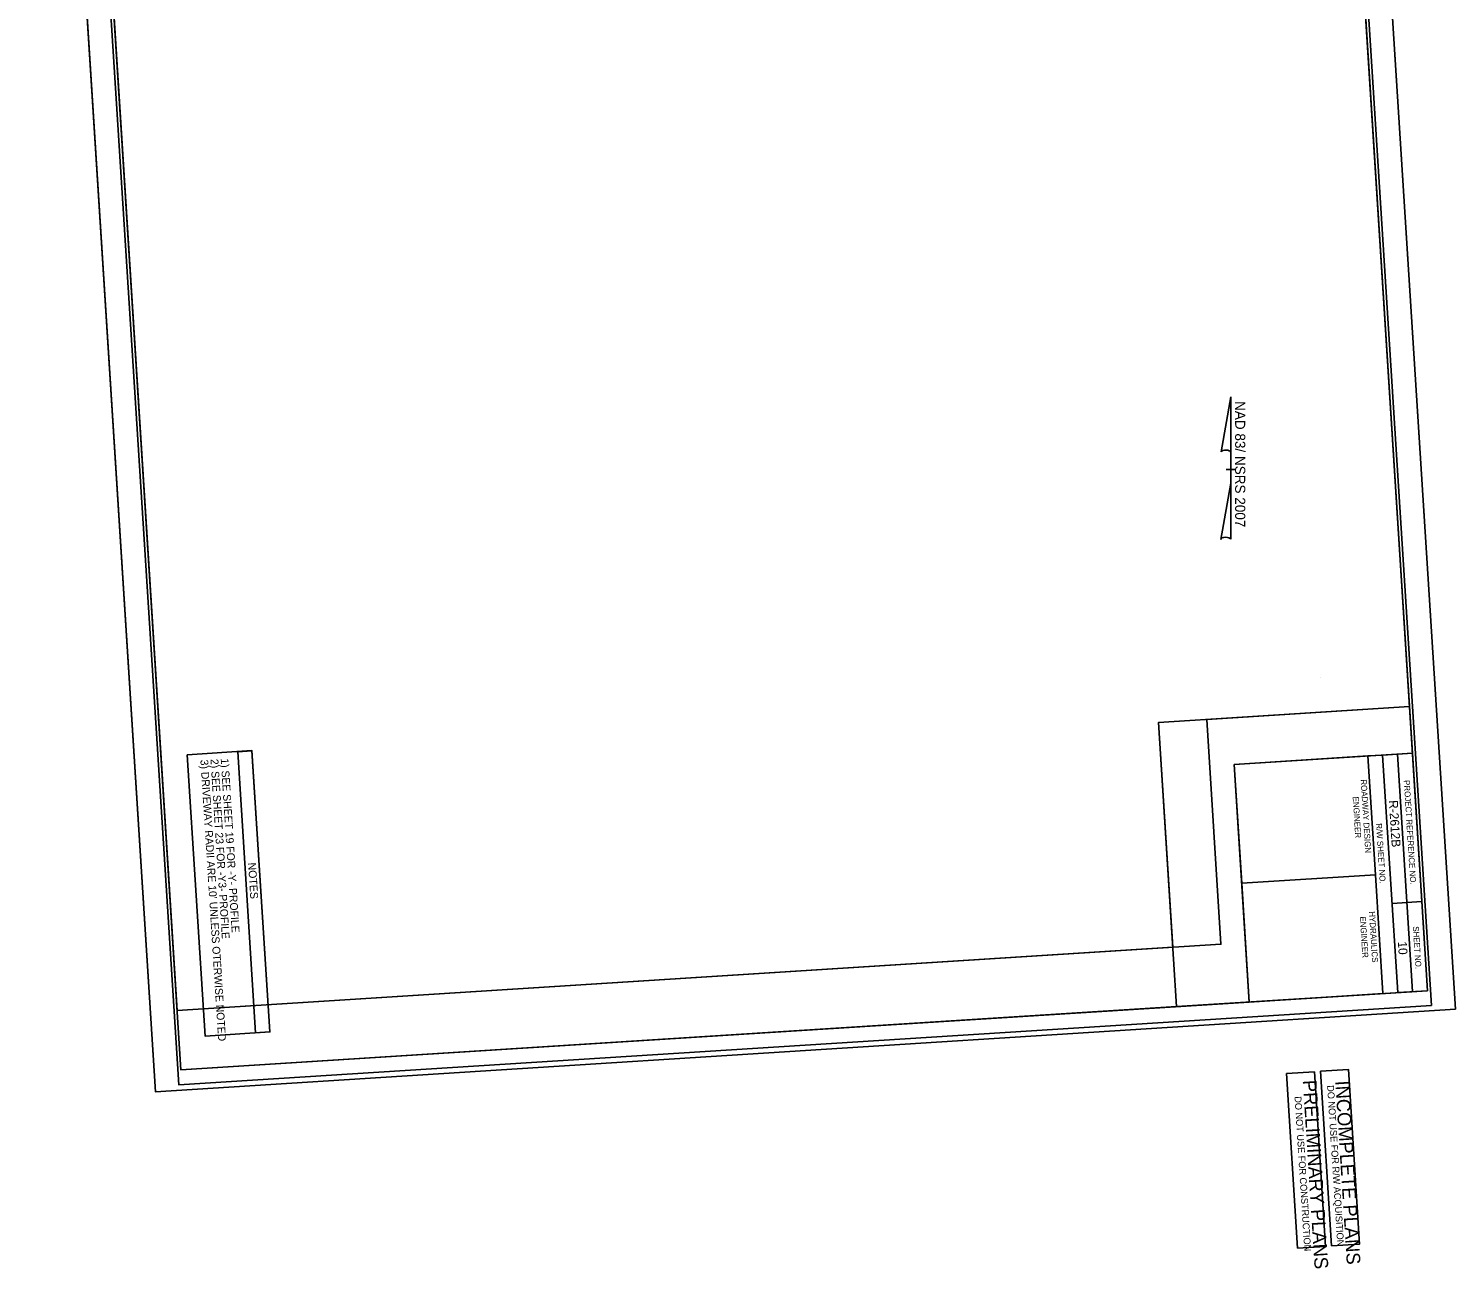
# Model space of a CAD drawing. Extents: x 1780418 to 1781618, y 810313 to 812397.
# Drawn here: x 1780418 to 1781618, y 810313 to 811355 of the extents above; entities that cross this region are included whole.
import ezdxf

# ---------------------------------------------------------------- set-up
doc = ezdxf.new("R2010")
doc.units = 0
for name, color, linetype in [('Prop Easement Aerial Utility', 7, 'Continuous'), ('Prop Easement Danger Tree Area', 7, 'Continuous'), ('Prop Easement Permanent Drainage', 7, 'Continuous'), ('Prop Easement Permanent Drainage Station Offsets', 7, 'Continuous'), ('Prop Easement Permanent Drainage Utility', 7, 'Continuous'), ('Prop Easement Permanent Drainage Utility Station Offsets', 7, 'Continuous'), ('Prop Easement Permanent Utility', 7, 'Continuous'), ('Prop Easement Temporary Drainage', 7, 'Continuous'), ('Prop Easement Temporary Drainage Station Offsets', 7, 'Continuous'), ('Prop Easement Temporary Utility', 7, 'Continuous'), ('Prop Parcel Number CELL', 7, 'Continuous'), ('Prop ROW CA Lines', 7, 'Continuous'), ('Prop ROW Marker CELL', 7, 'Continuous'), ('Prop ROW Station Offsets', 7, 'Continuous')]:
    doc.layers.add(name, color=color, linetype=linetype)

msp = doc.modelspace()

# ---------------------------------------------------------------- linework, layer by layer
at = {"layer": 'Prop Easement Aerial Utility'}
for p, q in [((1781617.8, 810530.9), (1781511, 812211)), ((1780418.2, 812141.5), (1780525, 810461.4))]:
    msp.add_line(p, q, dxfattribs=at)
at = {"layer": 'Prop Easement Danger Tree Area'}
msp.add_lwpolyline([(1781504.4, 810478.7), (1781527.9, 810480.1), (1781537.2, 810333.4), (1781513.7, 810332)], close=True, dxfattribs=at)
at = {"layer": 'Prop Easement Permanent Drainage'}
msp.add_lwpolyline([(1781475.8, 810476.7), (1781499.3, 810478.2), (1781508.6, 810331.5), (1781485.1, 810330)], close=True, dxfattribs=at)
at = {"layer": 'Prop Easement Permanent Drainage Utility'}
msp.add_line((1781504.5, 810809.4), (1781504.5, 810809.4), dxfattribs=at)
at = {"layer": 'Prop Easement Permanent Drainage Utility Station Offsets'}
for points in [[(1780551.7, 810744.8), (1780566.7, 810508.3), (1780621.1, 810511.7), (1780606, 810748.3)], [(1780594.1, 810747.2), (1780609.1, 810510.9), (1780621.1, 810511.7), (1780606, 810748)]]:
    msp.add_lwpolyline(points, close=True, dxfattribs=at)
at = {"layer": 'Prop Easement Permanent Utility'}
msp.add_lwpolyline([(1780454.4, 811926.9), (1780543.2, 810529.7), (1781380.1, 810582.9), (1781368.1, 810771.8), (1781579.1, 810785.2), (1781502.3, 811993.5)], close=True, dxfattribs=at)
at = {"layer": 'Prop Easement Temporary Drainage'}
for p, q in [((1781556.6, 810744.5), (1781544.1, 810743.7)), ((1781556.6, 810744.5), (1781569.3, 810544.8)), ((1781556.6, 810744.5), (1781569.3, 810544.8)), ((1781569.1, 810745.3), (1781581.8, 810545.6)), ((1781550.5, 810643.8), (1781438.2, 810636.7)), ((1781589.5, 810621.3), (1781564.5, 810619.7))]:
    msp.add_line(p, q, dxfattribs=at)
for points in [[(1781594.3, 810546.4), (1781499.2, 812043.4), (1780451.3, 811976.8), (1780546.4, 810479.8)], [(1780451.3, 811976.8), (1781499.1, 812043.4), (1781581.6, 810746.1), (1781431.9, 810736.5), (1781444.5, 810536.9), (1780546.4, 810479.8)], [(1781544.1, 810743.7), (1781550.5, 810643.8), (1781438.2, 810636.7), (1781431.9, 810736.5)], [(1781581.6, 810746.1), (1781594.3, 810546.4), (1781569.3, 810544.8), (1781556.6, 810744.5)], [(1781550.5, 810643.8), (1781556.8, 810544), (1781444.5, 810536.9), (1781438.2, 810636.7)]]:
    msp.add_lwpolyline(points, close=True, dxfattribs=at)
at = {"layer": 'Prop Easement Temporary Drainage Station Offsets'}
for p, q in [((1781420.8, 810999.3), (1781429, 811045.6)), ((1781429.1, 811045.6), (1781429, 811045.6)), ((1781429.1, 811045.6), (1781429, 811045.6)), ((1781429.1, 811045.6), (1781429.1, 810997.8)), ((1781429.1, 810973), (1781429.1, 810999.2)), ((1781429.1, 810997.8), (1781429.1, 810999.2)), ((1781425.1, 810984.6), (1781425, 810984.6)), ((1781425.1, 810984.6), (1781433.1, 810984.6)), ((1781428.6, 810984.6), (1781425.1, 810984.6)), ((1781429.1, 810973), (1781420.7, 810925.8)), ((1781429.1, 810926), (1781429.1, 810973))]:
    msp.add_line(p, q, dxfattribs=at)
for centre, start_param, end_param in [((1781424.9, 810998.8), 0.216388, 2.908219), ((1781424.9, 810925.6), 0.201328, 3.141593)]:
    msp.add_ellipse(centre, major_axis=(4.23, -0.03), ratio=0.461098, start_param=start_param, end_param=end_param, dxfattribs=at)
at = {"layer": 'Prop Easement Temporary Utility'}
for points in [[(1781499.1, 812043.4), (1780451.3, 811976.8), (1780546.4, 810479.8), (1781383.2, 810533), (1781368.1, 810771.8), (1781579.1, 810785.2)], [(1781368.1, 810771.8), (1781383.2, 810533), (1781594.3, 810546.4), (1781579.1, 810785.2)]]:
    msp.add_lwpolyline(points, close=True, dxfattribs=at)
at = {"layer": 'Prop ROW CA Lines'}
msp.add_lwpolyline([(1780418.2, 812141.5), (1780525, 810461.4), (1781617.8, 810530.9), (1781511, 812211)], close=True, dxfattribs=at)
at = {"layer": 'Prop ROW Marker CELL'}
msp.add_lwpolyline([(1781518.9, 811732.4), (1780459, 811854.7), (1780543.2, 810529.7), (1781420.7, 810585.5), (1781408.7, 810774.4), (1781579.1, 810785.2)], close=True, dxfattribs=at)
at = {"layer": 'Prop ROW Station Offsets'}
msp.add_lwpolyline([(1780439, 812129.8), (1780544.7, 810467.2), (1781597.6, 810534.1), (1781491.9, 812196.7)], close=True, dxfattribs=at)

# ---------------------------------------------------------------- texts
at = {"layer": 'Prop Easement Danger Tree Area'}
for s, height, p in [('DO NOT USE FOR R/W ACQUISITION', 5.76, (1781509.9, 810466.8)), ('INCOMPLETE PLANS', 11.52, (1781516.7, 810470.5))]:
    msp.add_text(s, height=height, rotation=273.6363, dxfattribs=at).set_placement(p)
at = {"layer": 'Prop Easement Permanent Drainage'}
for s, height, p in [('PRELIMINARY PLANS', 11.52, (1781489.4, 810471)), ('DO NOT USE FOR CONSTRUCTION', 5.76, (1781482.5, 810457.5))]:
    msp.add_text(s, height=height, rotation=273.6363, dxfattribs=at).set_placement(p)
at = {"layer": 'Prop Easement Permanent Drainage Station Offsets'}
for s, height, p in [("3) DRIVEWAY RADII ARE 10' UNLESS OTERWISE NOTED", 6.56, (1780562.7, 810740.4)), ('2) SEE SHEET 23 FOR -Y3- PROFILE', 6.56, (1780571.2, 810741)), ('1) SEE SHEET 19 FOR -Y- PROFILE ', 6.56, (1780579.8, 810741.5)), ('NOTES', 6.64, (1780602.8, 810653.9))]:
    msp.add_text(s, height=height, rotation=273.6363, dxfattribs=at).set_placement(p)
at = {"layer": 'Prop Easement Temporary Drainage'}
for s, p in [('ROADWAY DESIGN', (1781538.1, 810723.9)), ('PROJECT REFERENCE NO.', (1781574.3, 810723.3)), ('ENGINEER', (1781531.4, 810709.4)), ('R/W SHEET NO.', (1781551, 810687)), ('ENGINEER', (1781537.4, 810608.7)), ('HYDRAULICS', (1781545.1, 810613)), ('SHEET NO.', (1781582, 810600.4))]:
    msp.add_text(s, height=5, rotation=273.6363, dxfattribs=at).set_placement(p)
at = {"layer": 'Prop Easement Temporary Drainage Station Offsets'}
msp.add_text('NAD 83/ NSRS 2007', height=8.5, rotation=270, dxfattribs=at).set_placement((1781432.6, 811042))
at = {"layer": 'Prop Parcel Number CELL'}
for s, p in [('R-2612B  ', (1781561.8, 810706.3)), ('10', (1781569.4, 810587.6))]:
    msp.add_text(s, height=7.5, rotation=273.6363, dxfattribs=at).set_placement(p)

doc.saveas('drawing.dxf')
